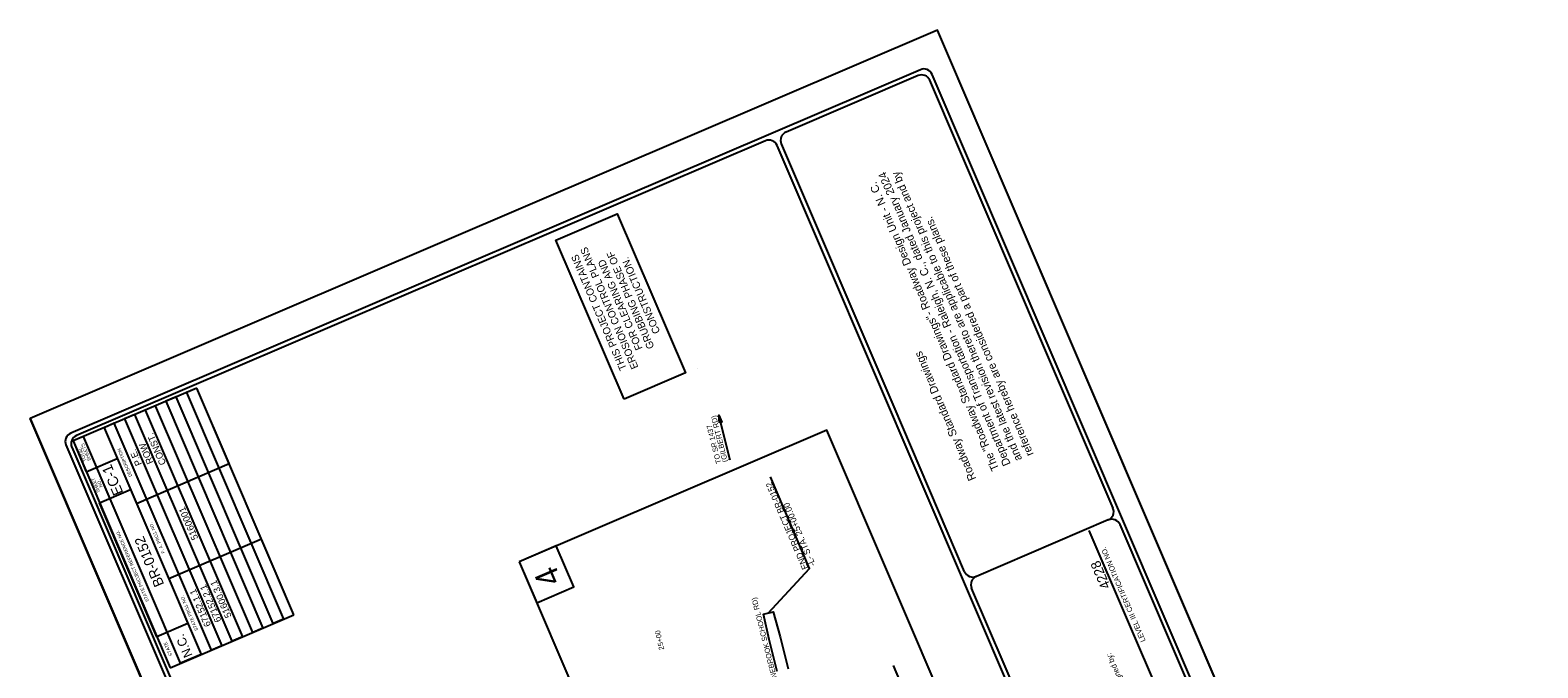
# Model space of a CAD drawing. Extents: x 1550250 to 1553148, y 808916 to 812359.
# Drawn here: x 1550250 to 1553148, y 811132 to 812359 of the extents above; entities that cross this region are included whole.
import ezdxf

# ---------------------------------------------------------------- set-up
doc = ezdxf.new("R2010")
doc.units = 0
for name, color, linetype in [('Old_Level_46', 7, 'Continuous'), ('P_RDY_DSN_Text', 7, 'Continuous'), ('P_RDY_Shade_Light', 7, 'Continuous'), ('Prop DSN Text', 7, 'Continuous'), ('Prop Terminator Cell', 7, 'Continuous'), ('Scratch_Level_0', 7, 'Continuous'), ('Sheet_Data_Field_CELL', 7, 'Continuous'), ('Sheet_Plan_CELL', 7, 'Continuous'), ('Sheet_Title_CELL', 7, 'Continuous')]:
    doc.layers.add(name, color=color, linetype=linetype)

msp = doc.modelspace()

# ---------------------------------------------------------------- linework, layer by layer
at = {"layer": 'Old_Level_46'}
msp.add_line((1551532, 811708.7), (1551532, 811708.7), dxfattribs=at)
msp.add_lwpolyline([(1551391.9, 811648.8), (1551260.8, 811954.9), (1551378.8, 812005.4), (1551509.9, 811699.2)], close=True, dxfattribs=at)
at = {"layer": 'P_RDY_DSN_Text'}
for points in [[(1551668.9, 811237.5), (1551748.5, 811322.9), (1551673, 811499.3)], [(1552046.5, 810930.6), (1551967.3, 811000.3), (1551909.6, 811136.6)]]:
    msp.add_lwpolyline(points, dxfattribs=at)
at = {"layer": 'P_RDY_Shade_Light'}
msp.add_line((1552498, 810901.3), (1552286.1, 811396.3), dxfattribs=at)
msp.add_lwpolyline([(1551686.2, 811124.8), (1551670.5, 811186.4), (1551659.6, 811235.2), (1551678.4, 811240), (1551691.9, 811191.8), (1551707.5, 811130.3)], dxfattribs=at)
at = {"layer": 'Prop DSN Text'}
msp.add_line((1551595.8, 811531.8), (1551573.9, 811618.1), dxfattribs=at)
at = {"layer": 'Prop Terminator Cell'}
msp.add_lwpolyline([(1551575, 811603.5), (1551573.9, 811618.1), (1551579.9, 811604.7), (1551577, 811605.8)], close=True, dxfattribs=at)
at = {"layer": 'Scratch_Level_0'}
for p, q in [((1551994.4, 812358.6), (1550250, 811611.9)), ((1553148.4, 809662.7), (1551994.4, 812358.6)), ((1551404, 808916), (1550250, 811611.9))]:
    msp.add_line(p, q, dxfattribs=at)
msp.add_lwpolyline([(1553148.4, 809662.7), (1551994.4, 812358.6), (1550250, 811611.9), (1551404, 808916)], close=True, dxfattribs=at)
at = {"layer": 'Sheet_Plan_CELL'}
for points in [[(1551190.2, 811336.1), (1551800.2, 809911.1), (1552391.4, 810164.1), (1551781.4, 811589.2)], [(1551190.2, 811336.1), (1551223.9, 811257.4), (1551295, 811287.9), (1551261.3, 811366.6)]]:
    msp.add_lwpolyline(points, close=True, dxfattribs=at)
at = {"layer": 'Sheet_Title_CELL'}
for p, q in [((1553086.3, 809698.2), (1551984, 812273.4)), ((1552196.2, 811756), (1551979.5, 812262.2)), ((1552747.8, 809656.4), (1551686.1, 812136.6)), ((1551910.7, 811633.8), (1551694.1, 812140)), ((1550570.4, 811670.2), (1550332.5, 811568.4)), ((1550570.4, 811670.2), (1550550.6, 811661.8)), ((1550757.1, 811234.1), (1550570.4, 811670.2)), ((1550632.6, 811524.8), (1550570.4, 811670.2)), ((1550491.1, 811636.3), (1550471.3, 811627.8)), ((1550677.8, 811200.2), (1550491.1, 811636.3)), ((1550530.8, 811653.3), (1550510.9, 811644.8)), ((1550510.9, 811644.8), (1550697.6, 811208.7)), ((1550717.4, 811217.2), (1550530.8, 811653.3)), ((1550550.6, 811661.8), (1550737.2, 811225.6)), ((1550451.5, 811619.3), (1550431.7, 811610.8)), ((1550431.7, 811610.8), (1550618.3, 811174.7)), ((1550638.2, 811183.2), (1550451.5, 811619.3)), ((1550471.3, 811627.8), (1550658, 811191.7)), ((1552046.3, 811317), (1551910.7, 811633.8)), ((1550352.3, 811576.9), (1550332.5, 811568.4)), ((1550539, 811140.8), (1550352.3, 811576.9)), ((1550411.8, 811602.4), (1550392, 811593.9)), ((1550392, 811593.9), (1550578.7, 811157.8)), ((1550598.5, 811166.3), (1550411.8, 811602.4)), ((1550318.9, 811560.7), (1551421.3, 808985.4)), ((1550330.3, 811556.2), (1551391.9, 809076.1)), ((1550332.5, 811568.4), (1550519.2, 811132.3)), ((1550332.5, 811568.4), (1550358, 811508.9)), ((1550358, 811508.9), (1550417.4, 811534.4)), ((1550454.2, 811448.4), (1550632.6, 811524.8)), ((1550383.4, 811449.5), (1550442.9, 811474.9)), ((1550442.9, 811474.9), (1550454.2, 811448.4)), ((1550493.7, 811191.8), (1550383.4, 811449.5)), ((1552322.7, 811416.6), (1552069, 811307.9)), ((1552322.7, 811416.6), (1552069, 811307.9)), ((1550694.9, 811379.5), (1550516.5, 811303.1)), ((1550757.1, 811234.1), (1550694.9, 811379.5)), ((1550516.5, 811303.1), (1550553.2, 811217.2)), ((1552266.8, 810801.6), (1552059.9, 811285.3)), ((1550519.2, 811132.3), (1550757.1, 811234.1)), ((1550553.2, 811217.2), (1550493.7, 811191.8)), ((1550697.6, 811208.7), (1550677.8, 811200.2)), ((1550737.2, 811225.6), (1550717.4, 811217.2)), ((1550618.3, 811174.7), (1550598.5, 811166.3)), ((1550658, 811191.7), (1550638.2, 811183.2)), ((1550578.7, 811157.8), (1550539, 811140.8))]:
    msp.add_line(p, q, dxfattribs=at)
for points in [[(1551961.4, 812282.5), (1550328, 811583.4)], [(1551956.9, 812271.2), (1551703.1, 812162.6)], [(1551663.5, 812145.6), (1550339.3, 811578.8)], [(1552331.8, 811439.2), (1552196.2, 811756)], [(1552552.2, 810923.8), (1552345.4, 811407.5)]]:
    msp.add_lwpolyline(points, dxfattribs=at)
for centre, start, end in [((1551963.6, 812255.3), 23.1736, 113.1736), ((1551968.1, 812266.7), 23.1736, 113.1736), ((1551709.8, 812146.7), 113.1736, 203.1736), ((1551670.2, 812129.8), 23.1736, 113.1736), ((1550334.7, 811567.5), 113.1736, 203.1736), ((1550346, 811562.9), 113.1736, 203.1736), ((1552315.8, 811432.4), 293.1736, 23.1736), ((1552329.4, 811400.7), 23.1736, 113.1736), ((1552062.1, 811323.8), 203.1736, 293.1736), ((1552075.7, 811292.1), 113.1736, 203.1736)]:
    msp.add_arc(centre, 17.2, start, end, dxfattribs=at)

# ---------------------------------------------------------------- texts
at = {"layer": 'Old_Level_46'}
for s, height, p in [('Department of Transportation - Raleigh, N. C., dated January 2024', 15.494, (1552135.2, 811524.3)), ('and the latest revision thereto are applicable to this project and by', 15.494, (1552157.3, 811533.7)), ('The "Roadway Standard Drawings"- Roadway Design Unit - N. C.', 15.494, (1552113.1, 811514.8)), ('reference hereby are considered a part of these plans.', 15.494, (1552179.4, 811543.2)), ('THIS PROJECT CONTAINS', 14.185, (1551397.1, 811707.7)), ('EROSION CONTROL PLANS', 14.185, (1551419.6, 811710.3)), ('GRUBBING PHASE OF', 14.185, (1551450.3, 811749)), ('FOR CLEARING AND', 14.185, (1551427.7, 811746.7)), ('CONSTRUCTION.', 14.185, (1551461.5, 811778.2)), ('Roadway Standard Drawings', 15.494, (1552068.8, 811495.9)), ('LEVEL III CERTIFICATION NO.', 10.053, (1552394.6, 811184.2)), ('4228', 18.92, (1552327.2, 811288.4)), ('Designed by:', 10.734, (1552360.5, 811084.8))]:
    msp.add_text(s, height=height, rotation=113.1736, dxfattribs=at).set_placement(p)
at = {"layer": 'P_RDY_DSN_Text'}
for s, height, rotation, p in [('END PROJECT BR-0152', 12, 113.1736, (1551746, 811324.3)), ('-L- STA. 25+00.00', 12, 113.1736, (1551760.2, 811330.4)), ('4', 45, 113.1736, (1551272, 811300.4)), ('-L-  SR 1436 (PINEBROOK SCHOOL RD)', 10, 104.2411, (1551709.9, 811017.1)), ('25+00', 10, 102.7833, (1551469.2, 811167.4))]:
    msp.add_text(s, height=height, rotation=rotation, dxfattribs=at).set_placement(p)
at = {"layer": 'Prop DSN Text'}
for s, p in [('(GILBERT RD)', (1551591.1, 811529.2)), ('TO SR 1437', (1551578.6, 811526))]:
    msp.add_text(s, height=10, rotation=104.262, dxfattribs=at).set_placement(p)
at = {"layer": 'Sheet_Data_Field_CELL'}
for s, height, p in [('CONST.', 12.94, (1550511.7, 811525.2)), ('P.E.', 12.94, (1550465.3, 811523.9)), ('ROW', 12.94, (1550487.4, 811527.2)), ('5160001', 12.94, (1550573.5, 811381.2)), ('BR-0152', 19.41, (1550507.9, 811292.9)), ('67152.2.1', 12.94, (1550617.9, 811222.8)), ('51600.3.1', 12.94, (1550637.7, 811231.3)), ('67152.1.1', 12.94, (1550598, 811214.3))]:
    msp.add_text(s, height=height, rotation=113.1736, dxfattribs=at).set_placement(p)
at = {"layer": 'Sheet_Title_CELL'}
for s, height, p in [('TOTAL', 6.47, (1550358.9, 811530.5)), ('SHEETS', 6.47, (1550367.4, 811531.7)), ('DESCRIPTION', 6.21, (1550446.2, 811501.1)), ('EC-1', 20, (1550429.4, 811469.1)), ('SHEET', 6.47, (1550384.7, 811470.9)), ('NO.', 6.47, (1550389.7, 811480.7)), ('F. A. PROJ. NO.', 6.21, (1550509.2, 811353.9)), ('STATE PROJECT REFERENCE NO.', 6.468, (1550478.9, 811260.6)), ('STATE PROJ. NO.', 6.21, (1550573, 811204.8)), ('STATE', 6.47, (1550523.6, 811156.3)), ('N.C.', 17.25, (1550562.6, 811156.3))]:
    msp.add_text(s, height=height, rotation=113.1736, dxfattribs=at).set_placement(p)

doc.saveas('drawing.dxf')
